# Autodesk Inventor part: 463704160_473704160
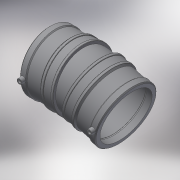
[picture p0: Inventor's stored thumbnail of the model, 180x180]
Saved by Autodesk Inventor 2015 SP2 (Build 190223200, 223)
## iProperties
Created: 2017-06
Part Number: 463704160_473704160
Material: Generic
Description: PLASSON 15° LIGHTFIT ELBOW 160
Document SubType Name: Modeling
Designer: KIM
Mass: 12693.1 g
Surface Area: 10598.3 cm^2
Volume: 12693.1 cm^3
Density: 1 g/cm^3
Appearance: Default
Author: KIM
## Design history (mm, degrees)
derived "473704.ipt"
feature "Solid1::473704.ipt"
tag "TaggingFeature1"
body "Solid1"
other parameters: "d14" = 17.6296, "d19" = 3.52592, "d20" = 168 deg, "d22" = 189.14, "d23" = 193, "d24" = 183.4658, "d25" = 135 deg, "d26" = 106.8, "d29" = 106, "d43" = 135 deg, "d45" = 10.68, "d47" = 8.01, "d48" = 189.14, "d49" = 193, "d50" = 0.965, "d51" = 94.57, "d52" = 165 deg, "d53" = 267, "d54" = 21.56, "d55" = 107.8, "d56" = 152, "d57" = 68.6, "d58" = 106, "d59" = 15, "d61" = 5 deg, "d63" = 4, "d64" = 14, "d65" = 0, "d67" = 165 deg, "d69" = 176, "d71" = 98, "d72" = 0, "d73" = 98, "d74" = 0, "d75" = 3, "d76" = 0, "L_" = 267, "L_1" = 98, "D_" = 193, "A_" = 106, "d_2" = 12
